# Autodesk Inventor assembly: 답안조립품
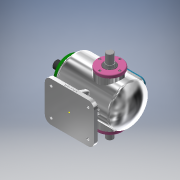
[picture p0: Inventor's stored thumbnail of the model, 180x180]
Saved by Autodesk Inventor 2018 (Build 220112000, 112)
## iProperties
Created: 2021-11
Part Number: 답안조립품
Material: 일반
Document SubType Name: Assembly
Designer: na
Author: na
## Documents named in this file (14)
- C:\Users\na\Desktop\711106V1038\답안조립품.iam
- C:\Users\na\Desktop\711106V1038\본체.ipt
- C:\Users\na\Desktop\711106V1038\베어링 6205.ipt
- 베어링 6205.ipt
- C:\Users\na\Desktop\711106V1038\축 커버.ipt
- C:\Users\na\Desktop\711106V1038\볼트 M4x0.7.ipt
- C:\Users\na\Desktop\711106V1038\오일실.ipt
- 오일실.ipt
- C:\Users\na\Desktop\711106V1038\편심축.ipt
- C:\Users\na\Desktop\711106V1038\슬라이드 커버.ipt
- C:\Users\na\Desktop\711106V1038\부시.ipt
- C:\Users\na\Desktop\711106V1038\상부커버.ipt
- C:\Users\na\Desktop\711106V1038\육각머리볼트 M4.ipt
- C:\Users\na\Desktop\711106V1038\슬라이드.ipt
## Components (12 placed, 1 different names)
1. M4x0.7:1
2. M4x0.7:2
3. M4x0.7:3
4. M4x0.7:4
5. M4x0.7:5
6. M4x0.7:6
7. M4x0.7:7
8. M4x0.7:8
9. M4x0.7:9
10. M4x0.7:10
11. M4x0.7:11
12. M4x0.7:12
